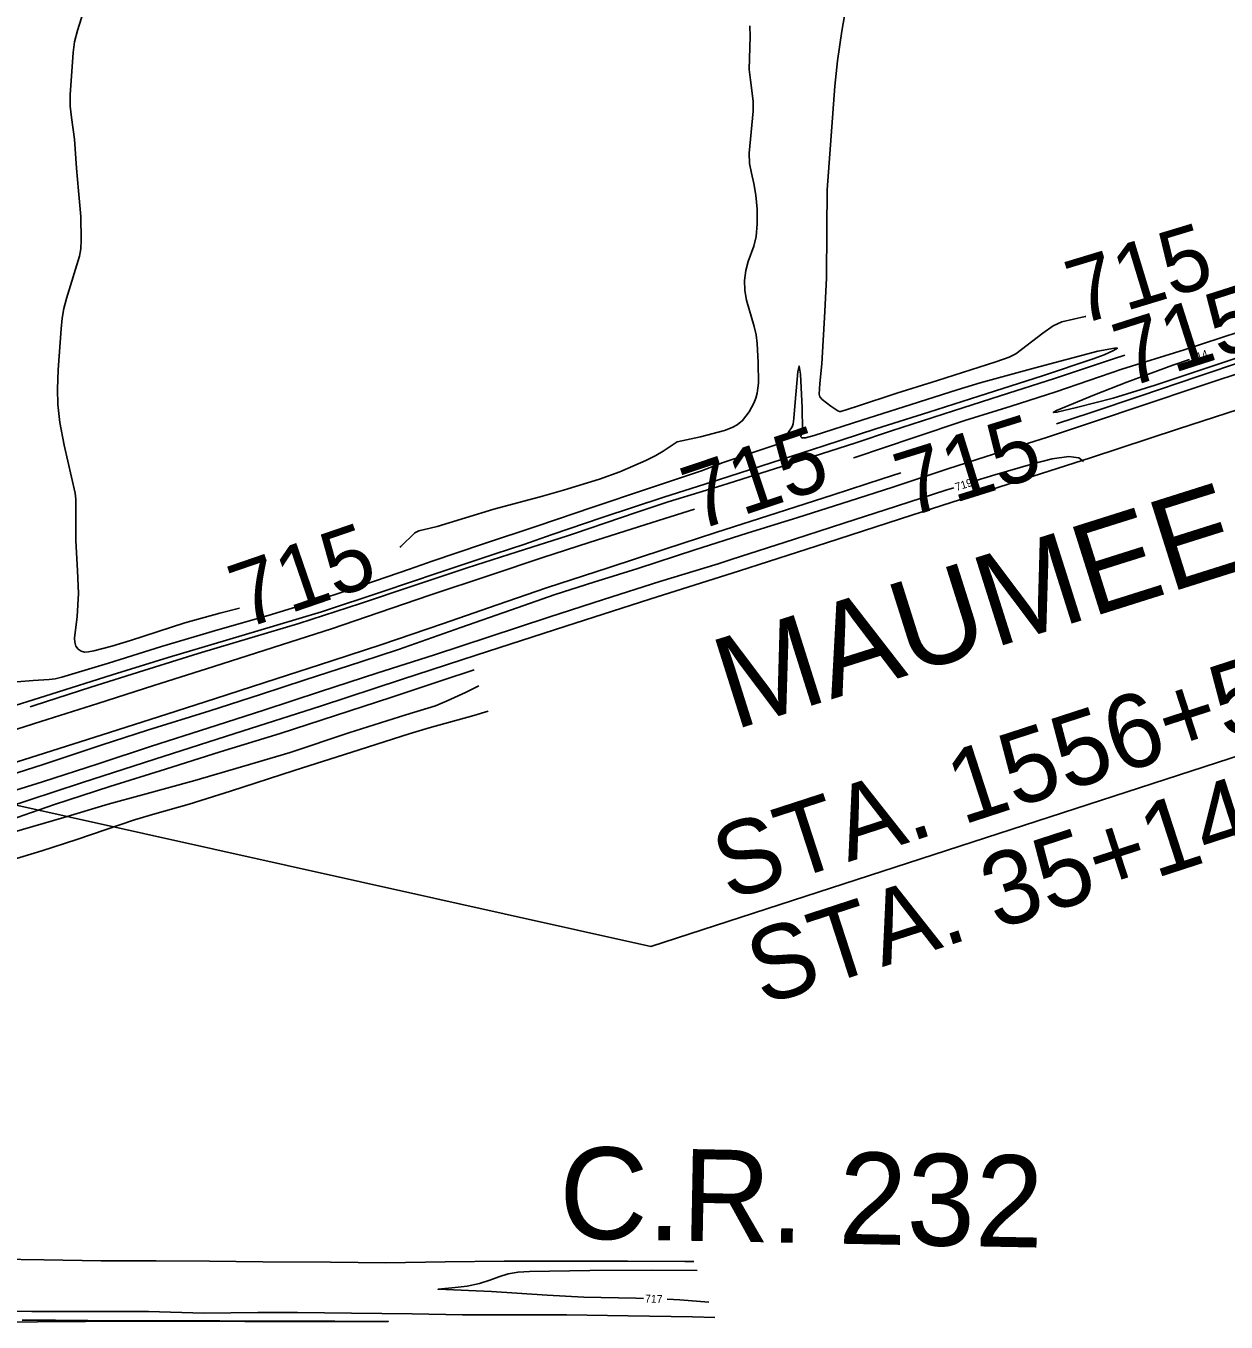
# Model space of a CAD drawing. Extents: x -468563856 to 36492962, y -306094093 to 11899197.
# Drawn here: x 1822443 to 1823055, y 530953 to 531615 of the extents above; entities that cross this region are included whole.
import ezdxf

# ---------------------------------------------------------------- set-up
doc = ezdxf.new("R2010")
doc.units = 0
for name, color, linetype in [('DT_X_Contour_Minor', 7, 'Continuous'), ('Level 14', 7, 'Continuous'), ('Level 19', 7, 'Continuous'), ('Level 40', 7, 'Continuous')]:
    doc.layers.add(name, color=color, linetype=linetype)

msp = doc.modelspace()

# ---------------------------------------------------------------- linework, layer by layer
at = {"layer": 'DT_X_Contour_Minor'}
for points in [[(1822551.67, 531317.68), (1822541.65, 531314.99), (1822523.88, 531310.12), (1822496.11, 531301.09), (1822486.67, 531298.18), (1822477.43, 531295.87), (1822474.79, 531295.36), (1822472.67, 531295.23), (1822470.91, 531295.65), (1822469.44, 531296.72), (1822468.32, 531298.29), (1822467.69, 531300.19), (1822467.61, 531302.31), (1822468.96, 531313.28), (1822469.55, 531325.04), (1822469.18, 531336.87), (1822468.23, 531352.03), (1822468.33, 531373.14), (1822467.85, 531376.3), (1822462.36, 531400.68), (1822460.16, 531412.23), (1822459.03, 531421.49), (1822458.84, 531429.31), (1822459.25, 531439.14), (1822460.72, 531460), (1822461.33, 531465.6), (1822462.17, 531470.53), (1822463.44, 531475.62), (1822470.15, 531497.13), (1822470.76, 531500.94), (1822470.99, 531505.28), (1822470.73, 531517.31), (1822469.69, 531530.52), (1822468.56, 531542.08), (1822467.59, 531556.76), (1822465.98, 531567.86), (1822465.43, 531573.69), (1822465.43, 531579.44), (1822466.82, 531601.06), (1822467.62, 531606.53), (1822469.07, 531612.22), (1822473.1, 531625.08)], [(1822983.34, 531466.42), (1822982.97, 531466.32), (1822971.05, 531463.69), (1822966.67, 531461.55), (1822961.38, 531457.89), (1822947.66, 531447.34), (1822944.26, 531445.58), (1822937.4, 531443.33), (1822907.67, 531433.7), (1822886.9, 531427.22), (1822866.34, 531420.5), (1822858.31, 531417.86), (1822857.65, 531417.85), (1822856.84, 531418.19), (1822853.35, 531420.62), (1822848.87, 531424.11), (1822847.68, 531425.36), (1822847.26, 531426.69), (1822847.7, 531432.17), (1822848.73, 531442.28), (1822850.22, 531468.89), (1822851.11, 531486.06), (1822851.18, 531510.77), (1822851.48, 531530.99), (1822853.42, 531558.6), (1822855.37, 531583.88), (1822856.76, 531596.72), (1822858.82, 531611.93), (1822860.9, 531623.67)], [(1822812, 531614.59), (1822812.18, 531609.2), (1822811.64, 531592.4), (1822812.23, 531586.88), (1822813.65, 531576.21), (1822813.62, 531571.03), (1822811.6, 531549.67), (1822811.87, 531544.41), (1822812.78, 531539.41), (1822814, 531534.19), (1822815.09, 531528.18), (1822815.69, 531521.06), (1822815.71, 531513.67), (1822815.14, 531507.12), (1822814.03, 531502.2), (1822811.19, 531494.4), (1822810.01, 531489.82), (1822809.32, 531484.75), (1822809.35, 531479.57), (1822810.23, 531474.65), (1822814.25, 531461.33), (1822815.12, 531457.05), (1822815.71, 531452.55), (1822816.3, 531442.93), (1822816.32, 531432.42), (1822815.66, 531427.27), (1822815, 531424.65), (1822814.07, 531422.11), (1822811.56, 531417.67), (1822808.28, 531413.32), (1822805.53, 531411.04), (1822803.01, 531409.72), (1822798.98, 531408.23), (1822786.89, 531405.03), (1822774.91, 531402.46), (1822772.35, 531400.8), (1822767.69, 531397.62), (1822763.96, 531395.45), (1822758.92, 531392.88), (1822745.74, 531387.16), (1822735.3, 531383.35), (1822717.01, 531377.85), (1822706.26, 531374.65), (1822681.4, 531368.12), (1822652.47, 531359.2), (1822643.24, 531357), (1822641.13, 531355.95), (1822634.02, 531349.1), (1822633.44, 531348.71)], [(1822864.84, 531394.23), (1822865.51, 531394.46), (1822895.7, 531404.69), (1822921.62, 531413.35), (1822945.29, 531420.57), (1822967.95, 531428.03), (1823001.63, 531439.54), (1823033.39, 531449.42), (1823061.54, 531458.59), (1823085.97, 531466.51), (1823112.8, 531475.09), (1823136.87, 531483.01), (1823165.87, 531492.65), (1823189.79, 531500.79), (1823214.61, 531509.5), (1823245.21, 531521.28), (1823271.75, 531530.93), (1823290.9, 531537.63), (1823319.88, 531546.38), (1823321.53, 531546.92)], [(1822438.09, 531280.09), (1822446.43, 531280.76), (1822454.62, 531281.16), (1822457.67, 531281.52), (1822461.11, 531282.33), (1822484.86, 531289.6), (1822511.9, 531298.02), (1822540.62, 531306.54), (1822566.41, 531313.93), (1822588.62, 531320.62), (1822609.21, 531327.5), (1822638.35, 531337.55), (1822650.05, 531341.65), (1822675.57, 531350.26), (1822703.92, 531359.57), (1822731.97, 531369.16), (1822759.28, 531378.33), (1822787.38, 531387.7), (1822798.36, 531391.94), (1822826.18, 531401.32), (1822828.06, 531402.31), (1822829.88, 531404.62), (1822833.57, 531410.09), (1822834.03, 531411.65), (1822834.45, 531414.34), (1822835.16, 531422.69), (1822836.39, 531438.17), (1822837.09, 531441.1), (1822837.74, 531436.88), (1822838.64, 531419.81), (1822838.75, 531408.61), (1822838.05, 531405.02), (1822838.46, 531404.41), (1822840.35, 531404.56), (1822844.83, 531405.74), (1822869.03, 531413.43), (1822890.5, 531420.32), (1822917.75, 531428.9), (1822929.41, 531432.5), (1822957.56, 531440.22), (1822989.48, 531448.7), (1822997.95, 531450.24), (1822999.41, 531450.19), (1822997.48, 531449.02), (1822992.69, 531446.78), (1822987.12, 531444.74), (1822961.16, 531436.19), (1822928.84, 531425.72), (1822903.22, 531417.64), (1822876.16, 531409), (1822849.65, 531400.37), (1822823.33, 531391.87), (1822795.93, 531383.11), (1822768.17, 531374.26), (1822736.71, 531363.91), (1822711.13, 531355.1), (1822696.64, 531350.11), (1822682.1, 531345.39), (1822653.1, 531335.61), (1822624.86, 531326.14), (1822593.58, 531315.74), (1822570.84, 531308.91), (1822545.14, 531301.33), (1822515.32, 531292.39), (1822486.76, 531283.55), (1822455.72, 531273.81), (1822428.5, 531265.23)], [(1823003.16, 531446.71), (1822997.4, 531444.82), (1822967.26, 531434.78), (1822939.67, 531425.92), (1822915.8, 531418.29), (1822884.3, 531408.08), (1822865.95, 531402), (1822831.57, 531390.8), (1822797.65, 531380.16), (1822770.31, 531371.76), (1822753.94, 531366.44), (1822722.51, 531355.67), (1822718.93, 531354.43), (1822693.36, 531346.41), (1822667.85, 531338.19), (1822639.33, 531328.65), (1822613.35, 531319.96), (1822582, 531309.71), (1822557.94, 531302.64), (1822530.56, 531294.45), (1822503, 531285.88), (1822475.97, 531277.38), (1822447.08, 531268.04), (1822444.98, 531267.25)], [(1823036.22, 531444.49), (1823027.76, 531441.59), (1823004.23, 531432.82), (1822987.74, 531426.42), (1822968.33, 531418.38), (1822966.7, 531417.38), (1822968.6, 531417.53), (1822978.63, 531419.9), (1822997.3, 531424.8), (1823018.7, 531431.4), (1823040.12, 531438.43), (1823065.6, 531446.94)], [(1823068.15, 531439.7), (1823041.39, 531430.8), (1823011.98, 531420.97), (1822988.33, 531412.98), (1822963.3, 531404.72), (1822932.54, 531394.95), (1822912.87, 531388.6), (1822884.83, 531379.26), (1822862.59, 531372.12), (1822836.39, 531363.77), (1822810.65, 531355.86), (1822783.89, 531347.33), (1822754.82, 531337.92), (1822732.39, 531330.87), (1822712.69, 531324.57), (1822690, 531316.66), (1822664.52, 531307.69), (1822632.86, 531296.53), (1822613.53, 531290.18), (1822585.28, 531281.08), (1822562.37, 531273.51), (1822536.56, 531265.16), (1822504.86, 531255.43), (1822481.66, 531247.95), (1822451.09, 531237.66), (1822425.97, 531229.73)], [(1822968.33, 531411.69), (1822985.59, 531417.29), (1823011.31, 531425.97), (1823040.41, 531435.84), (1823064.29, 531443.8)], [(1822982.15, 531392.41), (1822979.81, 531394.26), (1822974.62, 531394.97), (1822966.12, 531393.72), (1822956.22, 531391.28), (1822936.85, 531385.61), (1822927.48, 531382.65)], [(1822322.87, 531202.48), (1822336.81, 531207.01), (1822365.37, 531216.17), (1822388.93, 531223.69), (1822421, 531233.73), (1822452.26, 531243.68), (1822481.68, 531253.08), (1822514.64, 531263.6), (1822539.51, 531271.47), (1822570.49, 531281.53), (1822598.74, 531290.73), (1822624.33, 531299.06), (1822655.31, 531309.53), (1822683.2, 531319.25), (1822708.28, 531327.91), (1822740.17, 531338.35), (1822768.69, 531347.69), (1822794.6, 531356.17), (1822825.94, 531366.22), (1822854.4, 531375.36), (1822879.45, 531383.5), (1822889, 531386.64)], [(1822916.04, 531379.03), (1822912.4, 531377.88), (1822886.75, 531369.58), (1822859.99, 531360.88), (1822834.76, 531352.82), (1822802.38, 531342.4), (1822795.74, 531340.2), (1822766.06, 531331.14), (1822737.42, 531322.01), (1822709.4, 531312.99), (1822679.09, 531303.03), (1822651.2, 531293.87), (1822621.81, 531284.49), (1822593.01, 531275.06), (1822564.14, 531265.62), (1822535.53, 531256.41), (1822506.87, 531247.23), (1822479.66, 531238.22), (1822451.29, 531229.02), (1822427.15, 531221.52), (1822401.81, 531213.59)], [(1822419, 531249.64), (1822430.24, 531253.3), (1822450.44, 531259.76), (1822479.49, 531269.06), (1822508.08, 531278.13), (1822538.61, 531287.87), (1822568.86, 531297.55), (1822599.12, 531307.3), (1822616.53, 531313.24), (1822648.77, 531324.28), (1822679.48, 531334.41), (1822706.41, 531343.45), (1822730.03, 531351.17), (1822759, 531360.25), (1822783.74, 531368.07)], [(1822132.44, 531110.25), (1822145.7, 531114.41), (1822149.59, 531116.1), (1822157.97, 531119.11), (1822182.56, 531127.18), (1822210.23, 531136.13), (1822235.24, 531143.64), (1822260.34, 531151.8), (1822284.89, 531160.12), (1822311.53, 531168.93), (1822338.53, 531177.94), (1822366.96, 531187.21), (1822392.98, 531195.61), (1822415.55, 531202.84), (1822441.7, 531212.02), (1822457.43, 531217.42), (1822485.67, 531226.7), (1822513.96, 531235.56), (1822541.9, 531244.31), (1822572.45, 531253.71), (1822600.65, 531262.79), (1822628.9, 531272.08), (1822654.94, 531280.76), (1822671.39, 531286.17)], [(1822673.71, 531278.06), (1822666.95, 531274.54), (1822657.7, 531270.27), (1822651.63, 531267.81), (1822636.61, 531263.18), (1822607.4, 531254.03), (1822577.52, 531244.04), (1822559.65, 531238.69), (1822529, 531229.67), (1822502.24, 531222.43), (1822484.77, 531217.56), (1822462.06, 531210.89), (1822430.53, 531201.7)], [(1822417.02, 531183.69), (1822450.89, 531193.89), (1822468.69, 531199.53), (1822498.21, 531209.69), (1822508.56, 531212.72), (1822526.08, 531217.68), (1822547.13, 531224.22), (1822579.51, 531234.81), (1822608.96, 531244.08), (1822638.17, 531253.51), (1822648.38, 531256.65), (1822671.14, 531262.88), (1822678.59, 531265.01)], [(1822428.46, 530985.56), (1822451.89, 530985.22), (1822481.16, 530984.72), (1822509.16, 530984.66), (1822536.36, 530984.49), (1822563.58, 530984.22), (1822598.15, 530984), (1822626.28, 530983.78), (1822656.62, 530984.18), (1822686.69, 530984.48), (1822718.78, 530984.51), (1822749.67, 530984.54), (1822778.79, 530984.37), (1822783.42, 530984.38)], [(1822757.8, 530965.52), (1822753.85, 530965.65), (1822727.25, 530966.19), (1822708.61, 530967.27), (1822680.23, 530969.11), (1822653, 530970.22), (1822661.67, 530971.04), (1822667.83, 530971.85), (1822674.04, 530973.09), (1822679.34, 530974.78), (1822684.02, 530976.59), (1822688.66, 530978.09), (1822693.77, 530978.96), (1822699.6, 530979.34), (1822730.42, 530979.75), (1822762.53, 530979.91), (1822785.15, 530979.72)], [(1822791.14, 530963.7), (1822776.28, 530964.89), (1822769.79, 530965.11)], [(1822794.12, 530955.73), (1822782.7, 530956.14), (1822749.97, 530956.69), (1822718.48, 530957.1), (1822688.68, 530957.17), (1822665.37, 530957.2), (1822639.7, 530957.62), (1822608.82, 530958.02), (1822581.33, 530958.38), (1822561.15, 530958.37), (1822533.55, 530958.07), (1822505.37, 530958.85), (1822477.25, 530958.94), (1822445.87, 530958.89), (1822418.82, 530959.15)], [(1822440.93, 530954.38), (1822457.82, 530954.48), (1822474.34, 530954.35), (1822508.19, 530954.18), (1822541.66, 530954.07), (1822567.54, 530953.89), (1822600.3, 530953.93), (1822627.6, 530953.79), (1822617.33, 530953.78), (1822590.23, 530953.8), (1822554.4, 530953.78), (1822525.26, 530954.02), (1822495.45, 530953.91), (1822473.18, 530953.78), (1822448.66, 530953.62), (1822418.67, 530953.48)]]:
    msp.add_lwpolyline(points, dxfattribs=at)
at = {"layer": 'Level 14'}
msp.add_lwpolyline([(1823073.63, 531423.06), (1823030.5, 531409.05), (1822985.68, 531394.35), (1822939.53, 531379.41), (1822894.66, 531365.06), (1822851.08, 531350.86), (1822806.72, 531336.62), (1822761.03, 531322.25), (1822718.09, 531308.5), (1822672.37, 531293.63), (1822634.39, 531281.28), (1822592.94, 531267.67), (1822549.35, 531253.68), (1822508.57, 531240.66), (1822471.1, 531228.44), (1822444.29, 531219.73), (1822402.07, 531205.86)], dxfattribs=at)
at = {"layer": 'Level 40'}
for p, q in [((1822761.52, 531145.03), (1823552.24, 531401.74)), ((1822054.52, 531302.57), (1822761.52, 531145.03))]:
    msp.add_line(p, q, dxfattribs=at)

# ---------------------------------------------------------------- texts
at = {"layer": 'Level 19'}
for s, height, rotation, p in [('715', 33, 16.85642, (1822979.8, 531461.87)), ('715', 33, 17.73877, (1823004.42, 531429.92)), ('714', 4, 18.90761, (1823037.61, 531442.85)), ('715', 33, 17.34916, (1822892.64, 531363.77)), ('715', 33, 18.50081, (1822784.68, 531356.84)), ('719', 4, 17.5497, (1822917.34, 531377.35)), ('715', 33, 18.9248, (1822553.99, 531306.81)), ('717', 4, 358.05279, (1822758.47, 530963.5))]:
    msp.add_text(s, height=height, rotation=rotation, dxfattribs=at).set_placement(p)
at = {"layer": 'Level 40'}
for s, height, rotation, p in [('MAUMEE & WESTERN RR', 46.8, 17.51707, (1822803.63, 531255.29)), ('STA. 1556+50.00 U.S. 24 =', 37.5, 17.9864, (1822801.11, 531168.22)), ('STA. 35+14.08 C.R. 232', 37.5, 17.9864, (1822818.48, 531114.71)), ('C.R. 232', 46.8, 358.88653, (1822714.36, 530996.24))]:
    msp.add_text(s, height=height, rotation=rotation, dxfattribs=at).set_placement(p)

doc.saveas('drawing.dxf')
